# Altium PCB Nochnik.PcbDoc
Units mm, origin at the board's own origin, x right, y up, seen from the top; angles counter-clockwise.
Board outline 75.25 x 60.25 mm, 2 copper layers (Top Layer, Bottom Layer), stack 1.57 mm thick; 35 components, 27 nets, 114 pads, 16 vias.
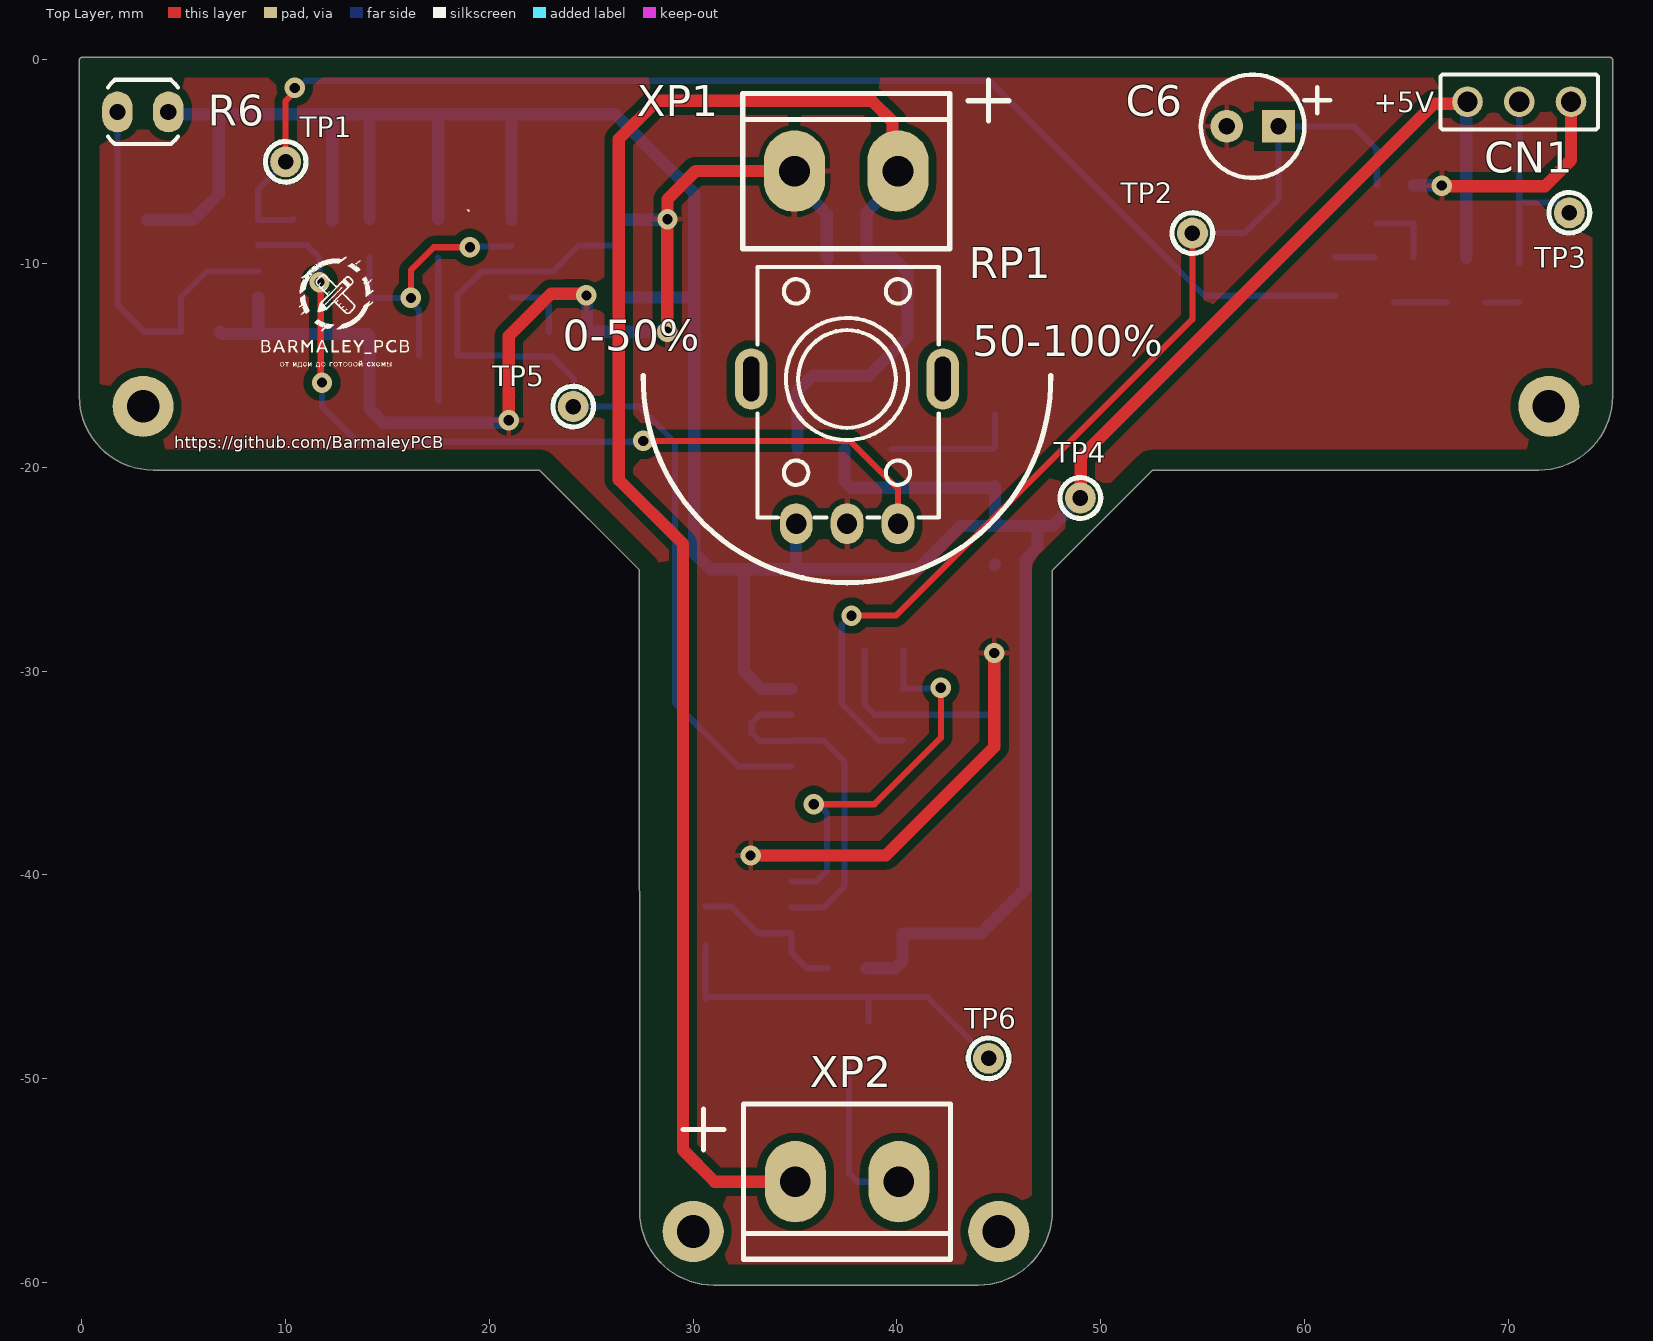
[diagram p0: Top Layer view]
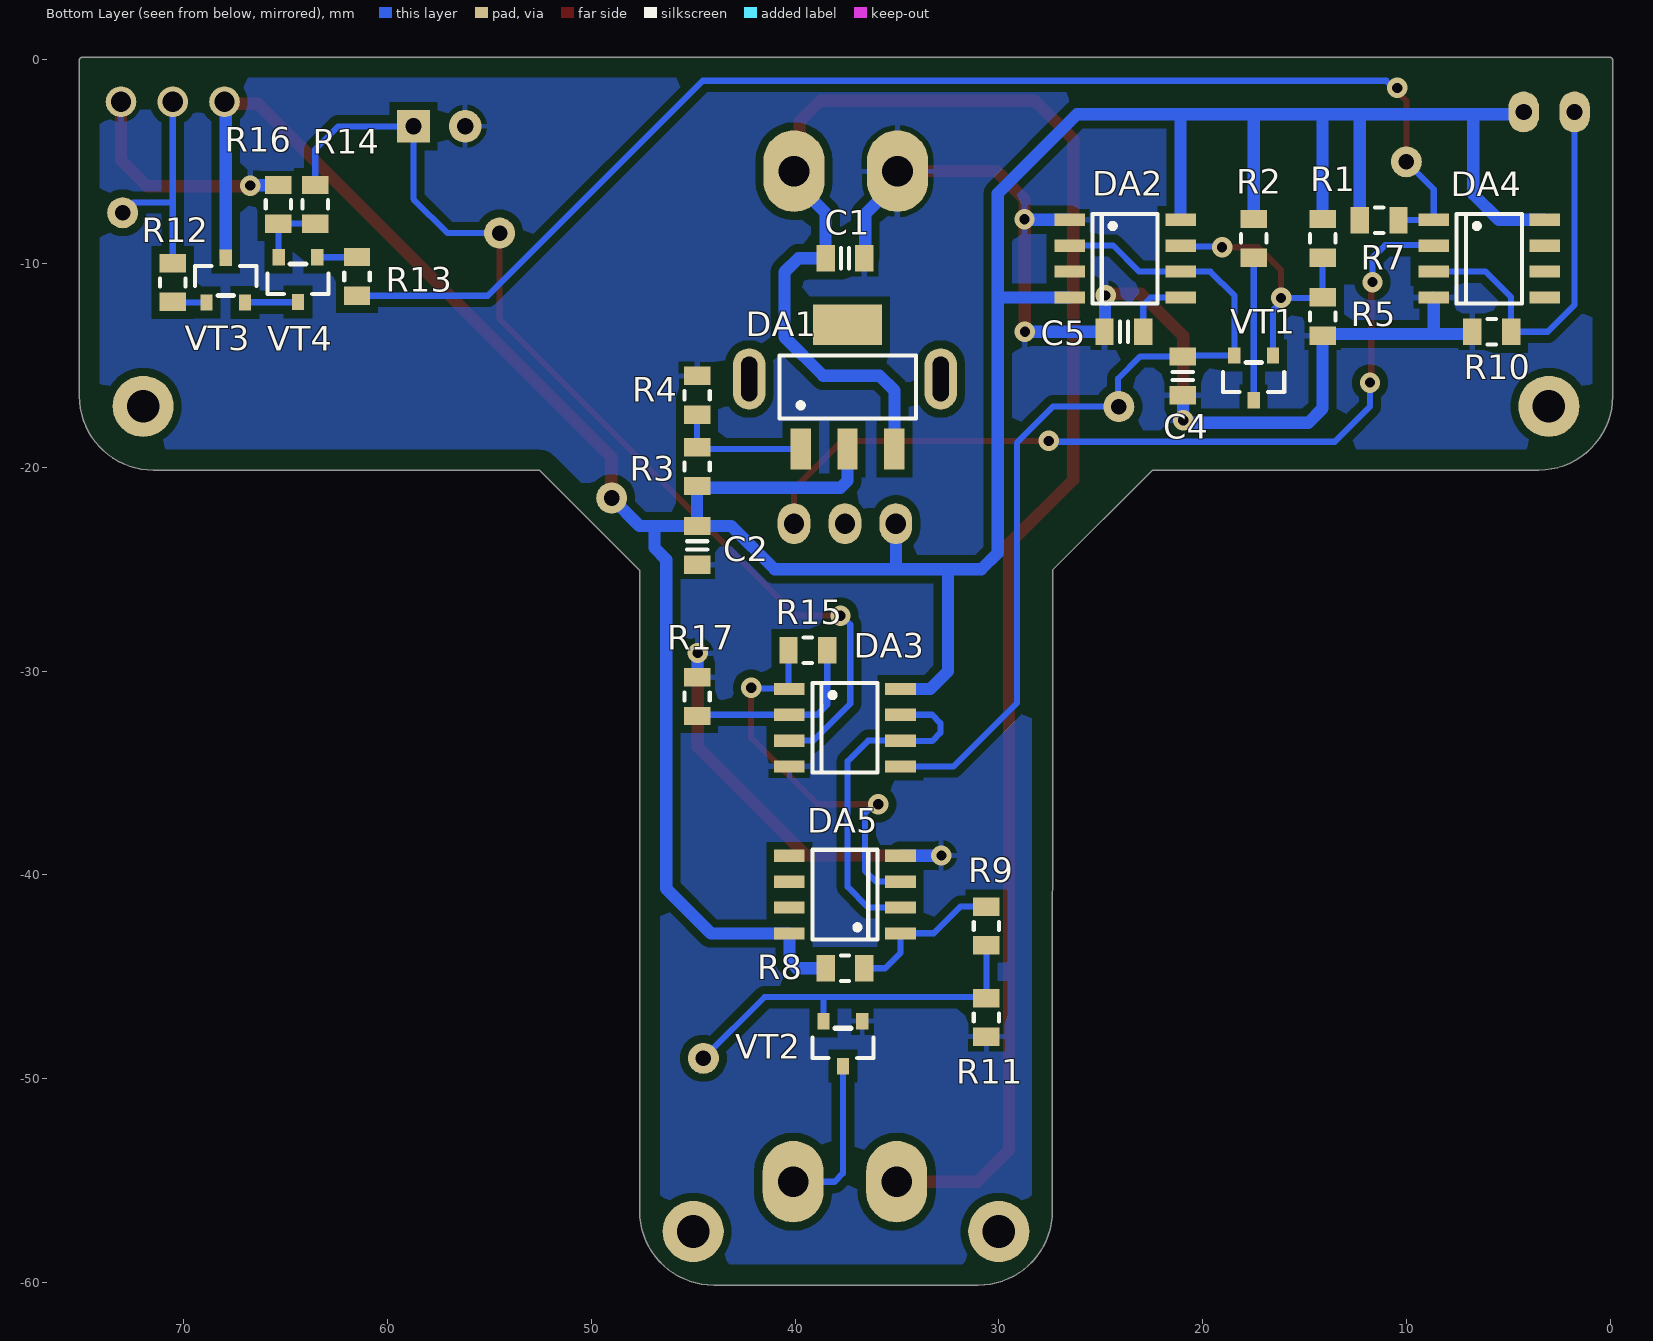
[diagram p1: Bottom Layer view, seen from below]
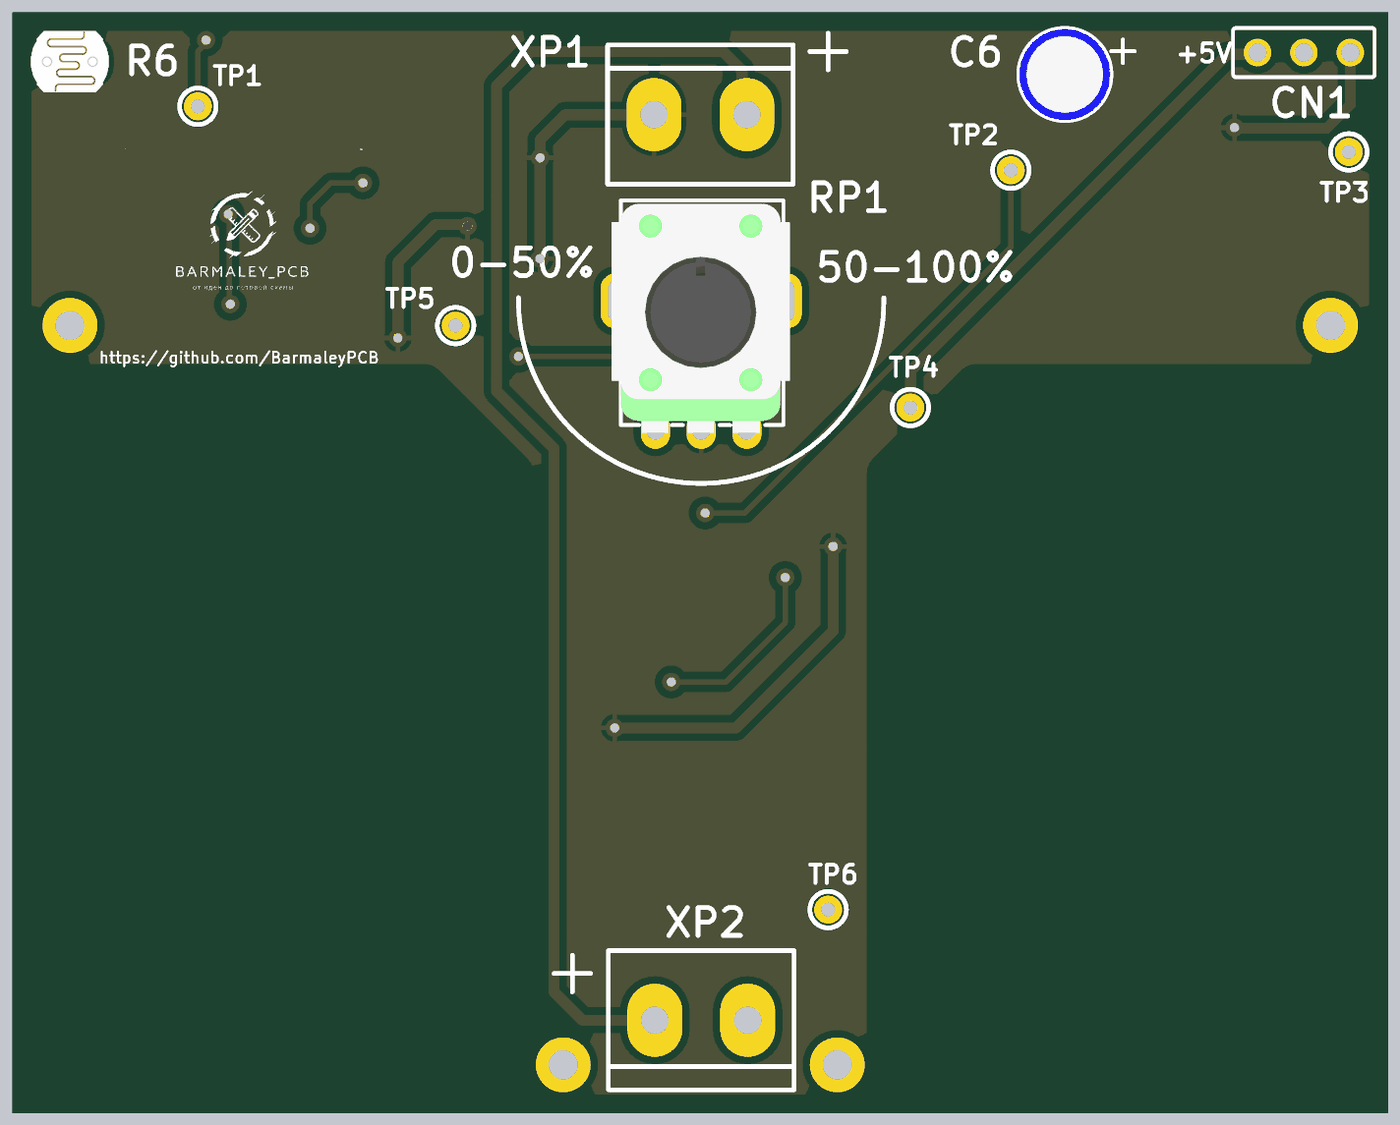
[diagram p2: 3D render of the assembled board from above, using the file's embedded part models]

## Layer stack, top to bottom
Top Solder: solder mask 0.0102, Solder Resist, Dk 3.5
Top Layer: signal copper 0.035
Dielectric 1: dielectric 1.5, FR-4, Dk 4.8
Bottom Layer: signal copper 0.035
Bottom Solder: solder mask 0.0102, Solder Resist, Dk 3.5

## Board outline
27.36,-25.04 22.447,-20.127 3.5,-20.127 cw(c3.5,-16.5) -0.127,-16.501 -0.127,-16.5 -0.127,0 cw(c0,0) 0,0.127 75,0.127 cw(c75,0) 75.127,0 75.127,-16.5 cw(c71.5,-16.5) 71.5,-20.127 52.551,-20.127 52.54,-20.14 47.627,-25.053 47.627,-56.5 cw(c44,-56.5) 44,-60.127 31,-60.127 cw(c31,-56.5) 27.373,-56.5

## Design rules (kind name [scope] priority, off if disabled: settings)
BoardOutlineClearance [All] p1: gap=1 ignorepadtopadclearanceinfootprint=FALSE
Clearance [All] p1: gap=0.4 ignorepadtopadclearanceinfootprint=FALSE
HoleSize [All] p1: absolutevalues=TRUE maxlimit=0.7 minlimit=0.7 maxpercent=80.000 minpercent=20.000
MinimumAnnularRing [All] p1: minimumring=1.1
PolygonConnect [All] p1: connectstyle=Relief reliefconductorwidth=0.254 reliefentries=4 polygonreliefangle="90 Angle" airgapwidth=0.254
RoutingVias [All] p1: holewidth=0.5 width=1 viastyle="Through Hole" minholewidth=0.5 minwidth=1 maxholewidth=0.5 maxwidth=1
SolderMaskExpansion [IsVia] p1: expansion=0.102 istentingtop=TRUE
SupplyNets "Schematic Supply Nets_2" [InNet('GND')] p1: voltage=0.000
SupplyNets "Schematic Supply Nets_1" [InNet('+12V')] p2: voltage=0.000
SupplyNets "Schematic Supply Nets" [InNet('+5V')] p3: voltage=0.000
Width Width_5 [InNet('GND')] p1: maxlimit=0.6 minlimit=0.6 preferedwidth=0.6
Width Width_4 [InNet('Net*_GND')] p2: maxlimit=0.6 minlimit=0.6 preferedwidth=0.6
Width Width_3 [InNet('Net*_+5V')] p3: maxlimit=0.6 minlimit=0.6 preferedwidth=0.6
Width Width_2 [InNet('+12V')] p4: maxlimit=0.6 minlimit=0.6 preferedwidth=0.6
Width Width_1 [InNet('+5V')] p5: maxlimit=0.6 minlimit=0.6 preferedwidth=0.6
Width [All] p6: maxlimit=0.3 minlimit=0.3 preferedwidth=0.3
29 further rules are at their usual default settings.

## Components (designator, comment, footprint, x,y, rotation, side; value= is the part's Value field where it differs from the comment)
C1 "0,1uF" CAP0805 37.551,-9.731 r90 bottom value=100nF
C2 "0,1uF" CAP0805 44.811,-23.822 r180 bottom value=100nF
C4 "1.5nF" CAP0805 20.979,-15.507 r180 bottom value=100nF
C5 "10nF" CAP0805 23.862,-13.34 r270 bottom value=100nF
C6 "" CAP_ELECTROLIT 57.332,-3.257 r180 top
CN1 "DS1023" PLS-3 70.543,-2.057 r0 top
DA1 "LM317" SOT-223 37.551,-18.97 r180 bottom
DA2 "NE555" NE555 23.804,-9.627 r180 bottom
DA3 "LM358" LM358 37.551,-32.775 r180 bottom
DA4 "LM393" LM393 5.93,-9.754 r180 bottom
DA5 "LM393" LM393 37.551,-40.965 r0 bottom
R1 "1kΩ" Res 14.108,-8.755 r180 bottom value=10K
R2 "1kΩ" Res 17.491,-8.755 r180 bottom value=10K
R3 "240Ω" Res 44.811,-19.958 r0 bottom value=10K
R4 "750Ω" Res 44.811,-16.457 r0 bottom value=10K
R5 "10kΩ" Res 14.108,-12.59 r180 bottom value=10K
R6 "10K" Photo_Res 2.993,-2.554 r180 top
R7 "10kΩ" Res 11.333,-7.87 r90 bottom value=10K
R8 "10kΩ" Res 37.551,-44.578 r90 bottom value=10K
R9 "100Ω" Res 30.606,-42.506 r180 bottom value=10K
R10 "10kΩ" Res 5.806,-13.34 r270 bottom value=10K
R11 "510kΩ" Res 30.606,-47 r180 bottom value=10K
R12 "10kΩ" Res 70.543,-10.925 r180 bottom value=10K
R13 "10kΩ" Res 61.5,-10.623 r0 bottom value=10K
R14 "47kΩ" Res 63.547,-7.087 r180 bottom value=10K
R15 "10kΩ" Res 39.372,-28.976 r90 bottom value=10K
R16 "1kΩ" Res 65.355,-7.087 r180 bottom value=10K
R17 "10kΩ" Res 44.811,-31.247 r180 bottom value=10K
RP1 "100kΩ" PR 37.551,-16.457 r0 top value=10k
VT1 "BC807" BC807 17.491,-15.607 r270 bottom
VT2 "2N7002" 2N7002 37.649,-48.287 r270 bottom
VT3 "BC817" BC817 67.942,-10.804 r90 bottom
VT4 "BC817" BC817 64.396,-10.784 r270 bottom
XP1 "TB-11A" TB-11A 37.051,-5.457 r270 top
XP2 "TB-11A" TB-11A 38.014,-55.056 r90 top

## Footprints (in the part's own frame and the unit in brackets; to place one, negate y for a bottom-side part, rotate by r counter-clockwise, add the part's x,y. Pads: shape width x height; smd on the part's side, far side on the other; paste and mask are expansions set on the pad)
2N7002 [mm]
  rect 0.8x0.6 smd: 1(-1.1,0.95) 2(-1.1,-0.95) 3(1.1,0)
  silkscreen extent -0.76,-1.5 0.7,1.5, body extent -1.25,-1.5 1.25,1.5, height 1.1
BC807 [mm]
  rect 0.8x0.6 smd: 1(-1.1,0.95) 2(-1.1,-0.95) 3(1.1,0)
  silkscreen extent -0.76,-1.5 0.7,1.5, body extent -1.25,-1.5 1.25,1.5, height 1.1
BC817 [mm]
  rect 0.8x0.6 smd: 1(-1.1,0.95) 2(-1.1,-0.95) 3(1.1,0)
  silkscreen extent -0.76,-1.5 0.7,1.5, body extent -1.25,-1.5 1.25,1.5, height 1.1
CAP0805 [mm]
  rect 1.3x0.9 smd: 1(0,-0.95) 2(0,0.95)
  silkscreen extent -0.5,-0.2 0.5,0.2, body extent -0.67,-1.05 0.67,1.05, height 0.8
CAP_ELECTROLIT [mm]
  round 1.6 hole 0.8: 1(1.143,0)
  rect 1.6x1.6 hole 0.8: 2(-1.397,0)
  silkscreen extent -3.94,-2.54 2.41,2.54, body extent -2.63,-2.5 2.37,2.5, height 11.9
LM358 [mm]
  rect 1.5x0.6 smd: 1(-2.725,1.905) 2(-2.725,0.635) 3(-2.725,-0.635) 4(-2.725,-1.905) 5(2.725,-1.905) 6(2.725,-0.635) 7(2.725,0.635) 8(2.725,1.905)
  silkscreen extent -1.6,-2.2 1.6,2.2, body extent -3,-2.5 3,2.5, height 1.75
LM393 [mm]
  rect 1.5x0.6 smd: 1(-2.725,1.905) 2(-2.725,0.635) 3(-2.725,-0.635) 4(-2.725,-1.905) 5(2.725,-1.905) 6(2.725,-0.635) 7(2.725,0.635) 8(2.725,1.905)
  silkscreen extent -1.6,-2.2 1.6,2.2, body extent -3,-2.5 3,2.5, height 1.75
NE555 [mm]
  rect 1.5x0.6 smd: 1(-2.725,1.778) 2(-2.725,0.508) 3(-2.725,-0.762) 4(-2.725,-2.032) 5(2.725,-2.032) 6(2.725,-0.762) 7(2.725,0.508) 8(2.725,1.778)
  silkscreen extent -1.6,-2.33 1.6,2.07, body extent -3,-2.63 3,2.37, height 1.75
Photo_Res [mm]
  oval 1.5x2 hole 0.8: 1(-1.25,0) 2(1.25,0)
  silkscreen extent -1.72,-1.58 1.72,1.58, body extent -2.14,-1.65 2.14,1.65, height 1.8
PLS-3 [mm]
  round 1.5 hole 1: 1(-2.54,0) 2(0,0) 3(2.54,0)
  silkscreen extent -3.87,-1.35 3.87,1.35, body extent -3.71,-1.2 3.81,1.2, height 8.4
PR [mm]
  oval 1.6x2 / inner round 1.4 / far side oval 1.6x2 hole 1: 1(-2.5,-6.3) 2(0,-6.3) 3(2.5,-6.3)
  oval 1.6x3 hole 0.8 slot 2.2 at 90 deg: ""(-4.7,0.8) ""(4.7,0.8)
  silkscreen extent -4.4,-6 4.5,6.3, body extent -4.9,-6.43 4.85,6.12, height 20.1
Res [mm]
  rect 1.3x0.9 smd: 1(0,-0.95) 2(0,0.95)
  silkscreen extent -0.63,-0.2 0.63,0.2, body extent -0.65,-1.05 0.65,1.05, height 0.4
SOT-223 [mm]
  rect 1x2 smd: 1(2.427,-0.129) 2(0.127,-0.129) 3(-2.173,-0.129)
  rect 3.4x2 smd: 4(0.127,5.971)
  silkscreen extent -3.22,1.37 3.48,4.47, body extent -3.22,-0.58 3.48,6.42, height 1.8
TB-11A [mm]
  oval 4x3 hole 1.5: 1(0,3) 2(0,-2.08)
  silkscreen extent -3.81,-4.62 3.81,5.54, body extent -3.81,-4.76 4.06,5.45, height 10

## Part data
C1 C2 C4 C5: library part Cap
C6: library part CAP_ELEC
CN1: library part TERMINAL_03P, "DS1023-1x4"
DA1: "SOT-223"
DA2: "NE555, SOIC8"
DA3 DA4 DA5: "LM358, SO8"
R1 R2 R3 R4 R5 R7 R8 R9 R10 R11 R12 R13 R14 R15 R16 R17: library part Res
R6: library part Photo_Res
RP1: library part CA6V, "Trimmer potentiometer CA6V"
XP1: "Клеммник 2-контактный, 5мм, прямой", Current="10 А", Operating Temperature Range="–40°C to +105°C", Voltage="250 В"
XP2: library part TB-11A_1, "Клеммник 2-контактный, 5мм, прямой", Current="10 А", Operating Temperature Range="–40°C to +105°C", Voltage="250 В"

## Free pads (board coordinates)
  round 1.524 hole 0.762: 6(10,-5) 6(24.108,-17.013) 6(44.5,-49) 6(49,-21.5) 6(54.5,-8.5) 6(73,-7.5)
  round 3 hole 1.6: M3(3,-17) M3(30,-57.5) M3(45,-57.5) M3(72,-17)

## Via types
v1: diameter 1, hole 0.5, Top Layer to Bottom Layer, tented both sides, 16 vias

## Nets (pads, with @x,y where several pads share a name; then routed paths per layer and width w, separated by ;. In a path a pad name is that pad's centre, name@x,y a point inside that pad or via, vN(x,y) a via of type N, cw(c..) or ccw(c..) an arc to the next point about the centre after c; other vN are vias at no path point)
+5V: C2.2 CN1.1 DA1.2 DA2.4 DA2.8 DA3.8 DA4.8 DA5.8 pad.6@49,-21.5 R1.2 R2.2 R3.2 R6.1 R7.2 R8.2 RP1.1 VT3.3 | length 183.2
  Top Layer w0.6: pad.6@49.017,-21.483 49.017,-19.483 66.353,-2.147 67.912,-2.147 CN1.1
  Bottom Layer w0.6: DA4.8 5.455,-7.849 6.712,-6.592 6.712,-2.661 ; R6.1@4.354,-2.661 12.296,-2.661 ; R7.2@12.299,-7.887 R7.2 12.283,-2.674 12.296,-2.661 ; R1.2 14.108,-2.769 14,-2.661 ; R2.2 17.491,-2.67 17.5,-2.661 ; DA2.8 21.079,-2.74 21,-2.661 ; DA2.4 29.897,-11.659 30.056,-11.5 ; DA3.8 33.37,-30.87 32.5,-30 32.5,-25 ; RP1.1 35.051,-24.949 35,-25 ; DA1.2 37.424,-20.649 37.775,-21 44.72,-21 R3.2 C2.2 ; R8.2@38.5,-44.577 R8.2 39.922,-44.578 40.278,-44.222 40.278,-42.87 40.902,-42.87 40.903,-42.869 44.126,-42.869 46.327,-40.667 46.327,-24.514 46.901,-23.94 46.901,-22.872 ; pad.6@49,-21.5 47.628,-22.872 46.901,-22.872 ; VT3.3@67.942,-9.703 67.942,-9.428 67.942,-2.117 CN1.1 ; 12.296,-2.661 14,-2.661 ; 14,-2.661 17.5,-2.661 ; 17.5,-2.661 21,-2.661 ; 21,-2.661 26.161,-2.661 30.056,-6.556 30.056,-11.5 ; 30.056,-11.5 30.056,-24.195 30.861,-25 32.5,-25 ; 32.5,-25 35,-25 ; 35,-25 41,-25 43.128,-22.872 C2.2 ; C2.2 46.901,-22.872
+12V: C1.2 DA1.1 XP1.1 XP2.1 | length 94
  Top Layer w0.6: XP2.1 31.056,-55.056 29.5,-53.5 29.5,-23.75 26.35,-20.599 26.35,-3.884 28.234,-2 38.762,-2 39.788,-3.026 39.788,-5.194 XP1.1
  Bottom Layer w0.6: DA1.1 35.124,-16.228 35.851,-15.5 38.613,-15.5 40.515,-13.598 40.515,-10.409 39.836,-9.731 C1.2 C1.2 38.5,-7.5 40.051,-5.949 XP1.1
GND: C1.1 C2.1 C4.1 C5.1 C6.1 CN1.3 DA2.1 DA3.4 DA4.4 DA5.4 R4.1 R5.1 R10.1 R11.1 R16.2 R17.2 RP1.2 VT2.1 XP1.2 | length 89.5
  Top Layer w0.6: v1(20.948,-17.688) 20.948,-13.552 23.021,-11.479 23.621,-11.479 23.623,-11.48 24.683,-11.48 v1(24.759,-11.557) ; v1(28.721,-13.343) 28.729,-13.335 28.729,-7.828 v1(28.737,-7.82) 28.737,-6.84 30.12,-5.457 XP1.2 ; v1(32.817,-39.046) 39.454,-39.046 44.774,-33.726 v1(44.774,-29.106) ; v1(66.741,-6.168) 66.769,-6.196 71.804,-6.196 73.083,-4.917 CN1.3
  Bottom Layer w0.6: R10.1 6.869,-13.453 8.5,-13.453 ; DA4.4 8.655,-13.299 8.5,-13.453 ; v1@20.948,-17.696 20.963,-17.68 20.963,-16.473 C4.1 ; v1(20.948,-17.688) 20.829,-17.807 18.08,-17.807 14.807,-17.807 14.108,-17.108 R5.1 14.022,-13.453 8.5,-13.453 ; v1(24.759,-11.557) 24.786,-11.583 24.786,-13.314 24.814,-13.342 28.719,-13.342 v1(28.721,-13.343) ; DA2.1 28.708,-7.849 v1(28.737,-7.82) ; v1(32.817,-39.046) 32.831,-39.06 DA5.4 ; XP1.2 34.971,-5.971 36.554,-7.554 36.554,-9.684 C1.1 ; v1(44.774,-29.106) 44.792,-29.124 44.792,-30.279 R17.2 ; C2.1@44.793,-24.79 C2.1 ; R16.2 65.371,-6.152 66.725,-6.152 v1(66.741,-6.168)
Net*_+5V: 
Net*_GND: 
Net*_OUT: 
NetC4_2: C4.2 DA2.2 DA2.6 DA3.5 pad.6@24.108,-17.013 VT1.2 | length 45.1
  Bottom Layer w0.3: pad.6@24.108,-17.013 pad.6@24.121,-17 ; DA2.2@26.514,-9.104 24.396,-9.104 23.111,-10.389 DA2.6 19.611,-10.389 18.441,-11.559 VT1.2 20.929,-14.507 C4.2 23.072,-14.557 24.15,-15.636 24.15,-16.971 pad.6@24.121,-17 ; DA3.5 32.236,-34.68 29.104,-31.549 29.104,-18.768 27.336,-17 pad.6@24.121,-17
NetC5_2: C5.2 DA2.5 | length 3.3
  Bottom Layer w0.3: DA2.5 22.541,-11.659 22.912,-12.03 C5.2
NetC6_2: C6.2 DA3.3 pad.6@54.5,-8.5 R14.2 | length 50.4
  Top Layer w0.3: v1(37.77,-27.275) 39.953,-27.275 54.5,-12.727 pad.6@54.5,-8.5
  Bottom Layer w0.3: v1@37.5,-27.5 37.291,-27.709 37.291,-31.599 39.102,-33.41 DA3.3 ; pad.6@54.5,-8.5 57.057,-8.5 58.729,-6.828 C6.2 ; C6.2@58.733,-3.26 62.421,-3.26 63.547,-4.387 R14.2
NetCN1_2: CN1.2 pad.6@73,-7.5 R12.2 | length 10.6
  Bottom Layer w0.3: R12.2 70.543,-7 ; CN1.2 70.543,-7 ; pad.6@73,-7.5 72.5,-7 70.543,-7
NetDA1_3: DA1.3 R3.1 R4.2 | length 6.6
  Bottom Layer w0.3: DA1.3 R3.1@44.735,-19.099 ; R3.1 R4.2
NetDA2_3: DA2.3
NetDA2_7: DA2.7 R1.1 R5.2 VT1.1 | length 13.8
  Top Layer w0.3: v1(16.143,-11.679) 16.143,-10.318 17.266,-9.195 v1(19.038,-9.195)
  Bottom Layer w0.3: R1.1 R5.2 14.148,-11.679 v1(16.143,-11.679) 16.143,-11.869 16.541,-12.266 VT1.1 ; v1(19.038,-9.195) 19.076,-9.157 21.02,-9.157 DA2.7@21.068,-9.108
NetDA3_1: DA3.1 DA5.3 R15.2 | length 19.4
  Top Layer w0.3: v1(35.916,-36.53) 38.891,-36.53 42.154,-33.266 v1(42.154,-30.811)
  Bottom Layer w0.3: DA5.3 36.026,-40.33 36.573,-39.784 36.573,-36.968 36.397,-36.792 36.368,-36.792 36.105,-36.53 v1(35.916,-36.53) ; DA3.1 DA3.1@40.305,-30.841 ; R15.2 40.322,-30.824 DA3.1@40.305,-30.841 ; v1(42.154,-30.811) 42.125,-30.841 DA3.1@40.305,-30.841
NetDA3_2: DA3.2 R15.1 R17.1 | length 9.3
  Bottom Layer w0.3: R15.1 38.422,-31.644 38.918,-32.14 DA3.2 44.748,-32.14 R17.1@44.811,-32.203
NetDA3_6: DA3.6 DA3.7 DA5.2 | length 16.9
  Bottom Layer w0.3: DA3.6@34.807,-33.428 33.278,-33.428 32.87,-33.02 32.87,-32.545 33.275,-32.14 DA3.7 ; DA5.2 36.4,-41.6 37.421,-40.579 37.421,-34.421 36.41,-33.41 DA3.6
NetDA4_1: DA4.1 pad.6@10,-5 R7.1 R13.2 | length 64.5
  Top Layer w0.3: pad.6@10,-5 10,-2.01 10.448,-1.562 v1(10.448,-1.373)
  Bottom Layer w0.3: pad.6@10,-5 8.655,-6.345 DA4.1 10.334,-7.849 R7.1@10.378,-7.805 ; v1(10.448,-1.373) 10.624,-1.373 10.974,-1.023 44.533,-1.023 55.083,-11.573 R13.2
NetDA4_2: DA4.2 RP1.3 | length 42.3
  Top Layer w0.3: v1(11.66,-10.905) 11.72,-10.965 11.72,-15.777 v1(11.779,-15.837) ; v1(27.55,-18.699) 27.554,-18.694 37.694,-18.694 40.051,-21.051 RP1.3
  Bottom Layer w0.3: DA4.2 8.683,-9.09 11.039,-9.09 11.66,-9.711 v1(11.66,-10.905) ; v1(11.779,-15.837) 11.779,-17.004 13.514,-18.738 27.51,-18.738 v1(27.55,-18.699)
NetDA4_3: DA4.3 R6.2 R10.2 | length 19.1
  Bottom Layer w0.3: R6.2 1.743,-12.025 3.058,-13.34 R10.2 ; R10.2@4.87,-13.325 4.87,-11.629 6.111,-10.389 DA4.3
NetDA5_1: DA5.1 R8.1 R9.2 | length 7.8
  Bottom Layer w0.3: R9.2 31.886,-41.556 33.192,-42.862 34.817,-42.862 34.817,-43.817 35.578,-44.578 R8.1
NetR2_1: R2.1 VT1.3 | length 7
  Bottom Layer w0.3: VT1.3@17.489,-16.706 R2.1@17.489,-9.706
NetR9_1: pad.6@44.5,-49 R9.1 R11.2 VT2.2 | length 18.8
  Bottom Layer w0.3: R9.1 R11.2 30.656,-46 38.458,-46 38.599,-46 41.5,-46 pad.6@44.5,-49 ; VT2.2@38.601,-47.185 38.601,-46.143
NetR12_1: R12.1 VT3.1 | length 1.7
  Bottom Layer w0.3: VT3.1 70.515,-11.904 R12.1
NetR13_1: R13.1 VT4.1 | length 2
  Bottom Layer w0.3: R13.1 61.511,-9.684 VT4.1
NetR14_1: R14.1 R16.1 VT4.2 | length 3.5
  Bottom Layer w0.3: R14.1 R16.1 65.346,-8.046 VT4.2
NetVT2_3: VT2.3 XP2.2 | length 7.9
  Bottom Layer w0.3: VT2.3 37.649,-54.649 38.056,-55.056 XP2.2
NetVT3_2: VT3.2 VT4.3 | length 2.6
  Bottom Layer w0.3: VT4.3 64.406,-11.894 66.982,-11.894 VT3.2
pads on no net: DA1.4 DA4.5 DA4.6 DA4.7 DA5.5 DA5.6 DA5.7 RP1.

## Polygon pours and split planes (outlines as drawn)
GND on Top Layer "GND_L01_P000" (solid, remove dead copper, pour order 0): 27.36,-25.04 22.447,-20.127 3.5,-20.127 cw(c3.5,-16.5) -0.127,-16.501 -0.127,-16.5 -0.127,0 cw(c0,0) 0,0.127 75,0.127 cw(c75,0) 75.127,0 75.127,-16.5 cw(c71.5,-16.5) 71.5,-20.127 52.551,-20.127 52.54,-20.14 47.627,-25.053 47.627,-56.5 cw(c44,-56.5) 44,-60.127 31,-60.127 cw(c31,-56.5) 27.373,-56.5
GND on Bottom Layer "GND_L02_P001" (solid, remove dead copper, pour order 1): 27.36,-25.04 22.447,-20.127 3.5,-20.127 cw(c3.5,-16.5) -0.127,-16.501 -0.127,-16.5 -0.127,0 cw(c0,0) 0,0.127 75,0.127 cw(c75,0) 75.127,0 75.127,-16.5 cw(c71.5,-16.5) 71.5,-20.127 52.551,-20.127 52.54,-20.14 47.627,-25.053 47.627,-56.5 cw(c44,-56.5) 44,-60.127 31,-60.127 cw(c31,-56.5) 27.373,-56.5

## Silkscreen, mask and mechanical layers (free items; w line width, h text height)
Top Overlay:
  drawing of 54 lines, arcs and shapes, not listed
  text "+5V" at 63.412,-2.561 h1
  text "TP1" at 10.7,-3.8 h1
  text "TP2" at 50.992,-7.044 h1
  text "TP3" at 71.284,-10.193 h1
  text "0-50%" at 23.608,-14.284 h1.52
  text "50-100%" at 43.692,-14.538 h1.52
  text "TP5" at 20.13,-16.007 h1
  text "https://github.com/BarmaleyPCB" at 4.534,-19.05 h0.6
  text "TP4" at 47.703,-19.774 h1
  text "TP6" at 43.293,-47.545 h1
Board:
  lines w0.254: 27.45,-24.95 22.5,-20 3.5,-20 cw(c3.5,-16.5) 0,-16.5 0,0 75,0 75,-16.5 cw(c71.5,-16.5) 71.5,-20 52.5,-20 ; 27.5,-25 27.5,-56.5 ccw(c31,-56.5) 31,-60 44,-60 ccw(c44,-56.5) 47.5,-56.5 47.5,-25 52.45,-20.05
